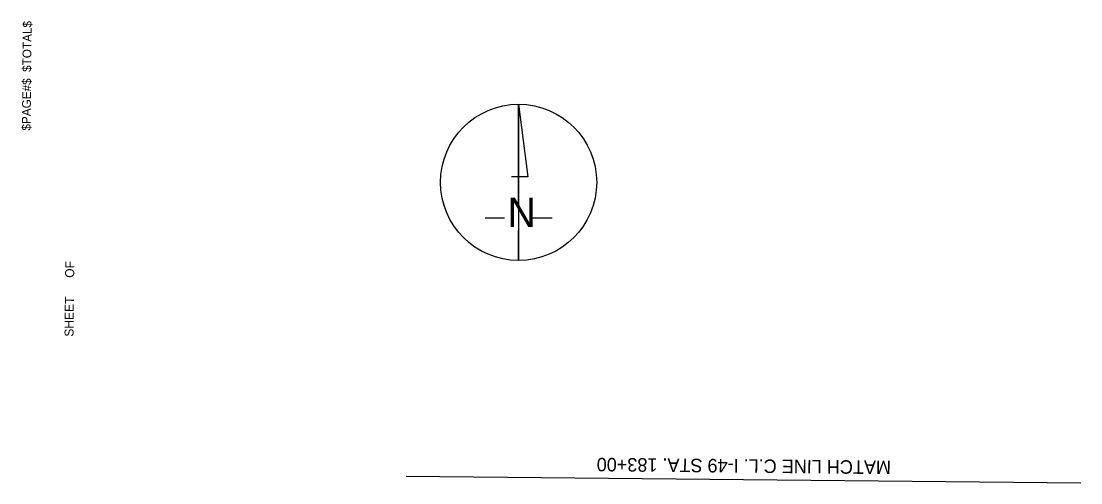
# Model space of a CAD drawing. Extents: x 631331 to 632745, y 372704 to 375744.
import ezdxf

# ---------------------------------------------------------------- set-up
doc = ezdxf.new("R2010")
doc.units = 0
for name, color, linetype in [('R_Border', 7, 'Continuous'), ('R_Border Notes', 7, 'Continuous'), ('R_Border_N Arrow', 7, 'Continuous'), ('R_No Plot', 7, 'Continuous')]:
    doc.layers.add(name, color=color, linetype=linetype)

msp = doc.modelspace()

# ---------------------------------------------------------------- linework, layer by layer
at = {"layer": 'R_Border'}
msp.add_line((631844.6, 375137), (632744.6, 375128.1), dxfattribs=at)
at = {"layer": 'R_Border_N Arrow'}
for p, q in [((631994.5, 375633.2), (632006.7, 375536.2)), ((631994.5, 375497.6), (631994.5, 375633.2)), ((631985.1, 375536.9), (632006.7, 375536.9)), ((631950, 375481.6), (631975.7, 375481.6)), ((632011.7, 375481.6), (632039.1, 375481.6)), ((631994.5, 375424.8), (631994.5, 375464.7))]:
    msp.add_line(p, q, dxfattribs=at)
at = {"layer": 'R_No Plot'}
msp.add_line((631994.5, 375633.2), (631994.5, 375424.8), dxfattribs=at)
msp.add_circle((631994.5, 375529), 104.2, dxfattribs=at)

# ---------------------------------------------------------------- texts
at = {"layer": 'R_Border'}
for s, p in [('$TOTAL$', (631344.1, 375676.3)), ('$PAGE#$', (631343.4, 375598))]:
    msp.add_text(s, height=11.72, rotation=89.4304, dxfattribs=at).set_placement(p)
at = {"layer": 'R_Border Notes'}
msp.add_text('MATCH LINE C.L. I-49 STA. 183+00', height=18, rotation=179.4304, dxfattribs=at).set_placement((632491.4, 375157.6))
at = {"layer": 'R_Border_N Arrow'}
msp.add_text('N', height=38.8, rotation=360, dxfattribs=at).set_placement((631979.8, 375469.6))
at = {"layer": 'R_No Plot'}
for s, p in [('OF', (631401.4, 375401.6)), ('SHEET', (631400.6, 375323))]:
    msp.add_text(s, height=12, rotation=89.4304, dxfattribs=at).set_placement(p)

doc.saveas('drawing.dxf')
